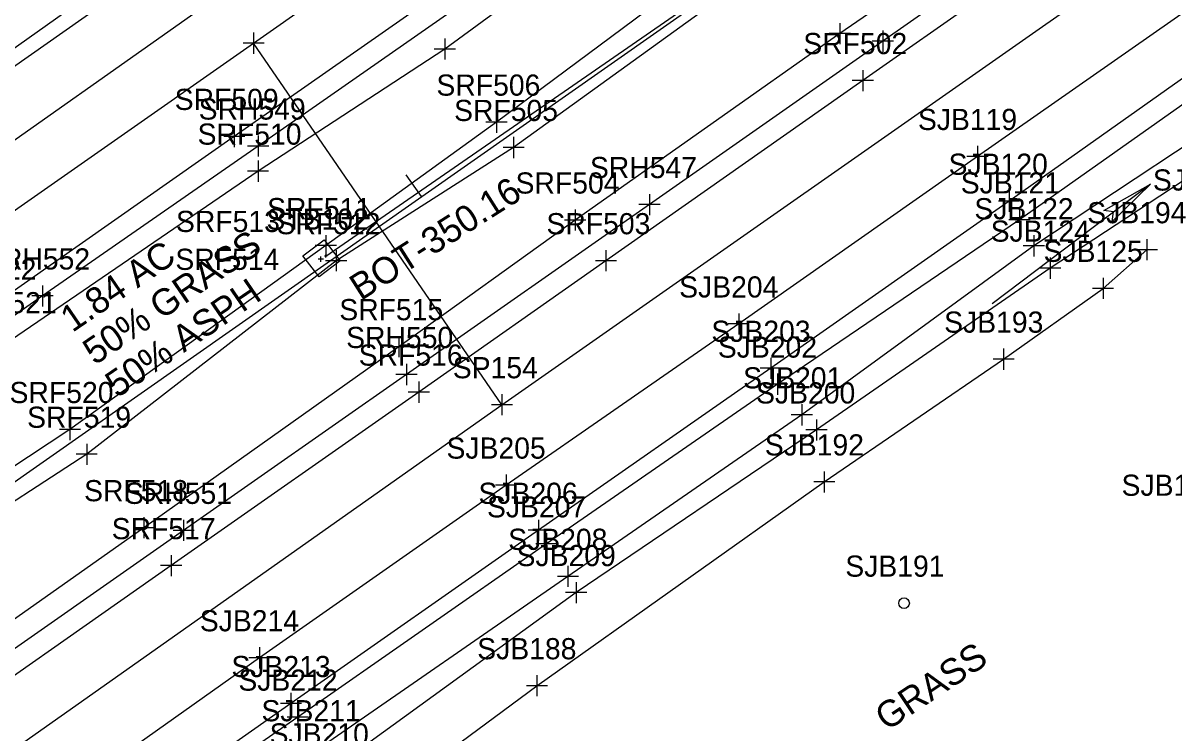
# Model space of a CAD drawing. Extents: x 941041 to 969446, y 397014 to 416764.
# Drawn here: x 951518.7 to 951736, y 402953.7 to 403087.8 of the extents above; entities that cross this region are included whole.
import ezdxf

# ---------------------------------------------------------------- set-up
doc = ezdxf.new("R2010")
doc.units = 0
for name, color, linetype in [('SURVEY - CENTERLINE - Preliminary', 7, 'Continuous'), ('SURVEY - CENTERLINE - Preliminary Curve Text', 7, 'Continuous'), ('SURVEY - DRAINAGE - Area Shapes', 7, 'Continuous'), ('SURVEY - DRAINAGE - Area Shapes - Points - Locators', 7, 'Continuous'), ('SURVEY - DRAINAGE - Area Shapes - Points - Numbers', 7, 'Continuous'), ('SURVEY - DRAINAGE - Area Shapes Text', 7, 'Continuous'), ('SURVEY - DRAINAGE - Pipes and Culverts', 7, 'Continuous'), ('SURVEY - DRAINAGE - Pipes and Culverts - Points - Locators', 7, 'Continuous'), ('SURVEY - DRAINAGE - Pipes and Culverts - Points - Numbers', 7, 'Continuous'), ('SURVEY - DRAINAGE - Storm Sewer', 7, 'Continuous'), ('SURVEY - DRAINAGE - Storm Sewer - Points - Numbers', 7, 'Continuous'), ('SURVEY - DTM - Breaklines', 7, 'Continuous'), ('SURVEY - DTM - Breaklines - Points - Locators', 7, 'Continuous'), ('SURVEY - DTM - Breaklines - Points - Numbers', 7, 'Continuous'), ('SURVEY - DTM - Spot Points - Locators', 7, 'Continuous'), ('SURVEY - DTM - Spot Points - Point Numbers', 7, 'Continuous'), ('SURVEY - MISCELLANEOUS - Bottom of MH and CB', 7, 'Continuous'), ('SURVEY - MISCELLANEOUS - Bottom of MH and CB - Points - Numbers', 7, 'Continuous'), ('SURVEY - TRANSPORTATION - Features', 7, 'Continuous'), ('SURVEY - TRANSPORTATION - Features - Points - Locators', 7, 'Continuous'), ('SURVEY - TRANSPORTATION - Features - Points - Numbers', 7, 'Continuous'), ('SURVEY - TRANSPORTATION - Roads', 7, 'Continuous'), ('SURVEY - TRANSPORTATION - Roads - Points - Locators', 7, 'Continuous'), ('SURVEY - TRANSPORTATION - Roads - Points - Numbers', 7, 'Continuous'), ('SURVEY - VEGETATION - Features with Text', 7, 'Continuous')]:
    doc.layers.add(name, color=color, linetype=linetype)

msp = doc.modelspace()

# ---------------------------------------------------------------- linework, layer by layer
at = {"layer": 'SURVEY - CENTERLINE - Preliminary'}
msp.add_line((950966.25, 402614.81), (953884.31, 404661.52), dxfattribs=at)
msp.add_line((950966.25, 402614.81), (953884.31, 404661.52), dxfattribs=at)
msp.add_line((950966.25, 402614.81), (953884.31, 404661.52), dxfattribs=at)
at = {"layer": 'SURVEY - CENTERLINE - Preliminary Curve Text'}
msp.add_line((951593.88, 403055.03), (951591.01, 403059.12), dxfattribs=at)
at = {"layer": 'SURVEY - DRAINAGE - Area Shapes'}
msp.add_line((951609.08, 403015.7), (951562.19, 403084.02), dxfattribs=at)
for points in [[(951145.6, 402792.15), (951562.19, 403084.02), (952475.83, 403724.71), (952754.77, 403922.8), (952578.99, 403846.21), (952455.44, 403792), (952334.19, 403750.29), (951972.51, 403632.53), (951887.41, 403584.59)], [(950765.73, 402528.11), (950855.07, 402487.28), (951056.09, 402625.14), (951609.08, 403015.7), (952524.78, 403657.05), (952475.83, 403724.71)]]:
    msp.add_lwpolyline(points, dxfattribs=at)
at = {"layer": 'SURVEY - DRAINAGE - Area Shapes - Points - Locators'}
for p, q in [((951562.19, 403086.02), (951562.19, 403082.02)), ((951564.19, 403084.02), (951560.19, 403084.02)), ((951609.08, 403017.7), (951609.08, 403013.7)), ((951611.08, 403015.7), (951607.08, 403015.7))]:
    msp.add_line(p, q, dxfattribs=at)
at = {"layer": 'SURVEY - DRAINAGE - Area Shapes Text'}
msp.add_line((951731.53, 403057.41), (951701.62, 403034.77), dxfattribs=at)
msp.add_lwpolyline([(951731.53, 403057.41), (951724.28, 403050.34), (951724.56, 403052.13), (951722.74, 403052.38)], close=True, dxfattribs=at)
msp.add_lwpolyline([(951731.53, 403057.41), (951724.28, 403050.34), (951724.56, 403052.13), (951722.74, 403052.38), (951731.53, 403057.41)], dxfattribs=at)
at = {"layer": 'SURVEY - DRAINAGE - Pipes and Culverts'}
msp.add_lwpolyline([(951575.84, 403043.76), (951765.83, 403175.23), (951951.92, 403216.39)], dxfattribs=at)
at = {"layer": 'SURVEY - DRAINAGE - Pipes and Culverts - Points - Locators'}
for p, q in [((951576.09, 403043.76), (951575.59, 403043.76)), ((951575.84, 403043.51), (951575.84, 403044.01)), ((951575.84, 403043.76), (951575.84, 403043.76)), ((951575.84, 403043.76), (951575.84, 403043.76))]:
    msp.add_line(p, q, dxfattribs=at)
at = {"layer": 'SURVEY - DRAINAGE - Storm Sewer'}
msp.add_line((951575.01, 403043.34), (951575.01, 403043.34), dxfattribs=at)
msp.add_lwpolyline([(951574.55, 403039.84), (951571.51, 403043.81), (951575.48, 403046.85), (951578.52, 403042.88), (951574.55, 403039.84)], dxfattribs=at)
at = {"layer": 'SURVEY - DTM - Breaklines'}
msp.add_line((951722.58, 403037.69), (951730.83, 403044.99), dxfattribs=at)
for points in [[(951854.25, 403319.66), (951811.69, 403290.89), (951768.65, 403259.5), (951723.04, 403227.57), (951679.29, 403196.14), (951634.6, 403164.93), (951590.23, 403133.88), (951544.48, 403102.6), (951498.11, 403069.66), (951452.15, 403038.35), (951433.07, 403025.21), (951424.63, 403019.72), (951420.03, 403018.11), (951422.38, 403023.89), (951430.59, 403035.7)], [(951836.08, 403227.91), (951793.18, 403197.31), (951749.92, 403170.47), (951703.64, 403135.64), (951660.15, 403107.9), (951608.06, 403069.1), (951575.82, 403045.76)], [(951839.65, 403222.38), (951797.17, 403192.37), (951753.33, 403165.09), (951706.67, 403131.34), (951664.15, 403102.54), (951611.28, 403064.31), (951577.76, 403042.92)], [(951882.64, 403166.97), (951846.32, 403142.14), (951845.34, 403140.85), (951800.52, 403105.06), (951758.25, 403071.51), (951712.6, 403041.51), (951668.47, 403010.93), (951623.1, 402980.2), (951576.62, 402946.49), (951535.08, 402916.86), (951489.08, 402884.22), (951442.46, 402851.9), (951396.06, 402820.24), (951353.64, 402790.7), (951305.86, 402756.61)], [(951846.17, 403143.63), (951798.24, 403106.85), (951755.36, 403076.11), (951709.52, 403045.74), (951665.69, 403013.78), (951621.55, 402983.27), (951574.76, 402950.88), (951533.18, 402922.12), (951486.76, 402887.78), (951441.32, 402857.8), (951393.85, 402824.12), (951350.68, 402794.89), (951304.42, 402761.09), (951261.65, 402730.04), (951245.94, 402719.49)], [(951575.82, 403045.76), (951527.52, 403011.01), (951480.03, 402979.65), (951432.25, 402944.1), (951384.56, 402912.98), (951337.64, 402877.72), (951288.98, 402848.05), (951240.98, 402812.92), (951195.6, 402783.43), (951143.39, 402744.95), (951093.24, 402715.77), (951046.95, 402677.96), (950999.14, 402648.78), (950948.74, 402611.17), (950902.47, 402579.09), (950854.68, 402542.03)], [(951577.76, 403042.92), (951530.68, 403006.34), (951482.65, 402975.12), (951435.54, 402939.25), (951387.56, 402907.68), (951341.21, 402872.58), (951293.73, 402840.01), (951246.54, 402805.47), (951199.41, 402776.68), (951147.67, 402739.07), (951099.33, 402706.23), (951051.58, 402671.4), (951004.7, 402639.99), (950954.22, 402602.88), (950907.42, 402570.91)], [(951291.86, 402744.42), (951338.46, 402771.86), (951384.81, 402800.53), (951428.6, 402828.85), (951473.25, 402860.72), (951518.66, 402892.2), (951567.96, 402927.23), (951615.69, 402962.6), (951669.94, 403001.11), (951703.81, 403024.31), (951722.58, 403037.69)]]:
    msp.add_lwpolyline(points, dxfattribs=at)
at = {"layer": 'SURVEY - DTM - Breaklines - Points - Locators'}
for p, q in [((951608.06, 403071.1), (951608.06, 403067.1)), ((951610.06, 403069.1), (951606.06, 403069.1)), ((951611.28, 403066.31), (951611.28, 403062.31)), ((951613.28, 403064.31), (951609.28, 403064.31)), ((951575.82, 403047.76), (951575.82, 403043.76)), ((951709.52, 403047.74), (951709.52, 403043.74)), ((951577.82, 403045.76), (951573.82, 403045.76)), ((951711.52, 403045.74), (951707.52, 403045.74)), ((951730.83, 403046.99), (951730.83, 403042.99)), ((951577.76, 403044.92), (951577.76, 403040.92)), ((951712.6, 403043.51), (951712.6, 403039.51)), ((951732.83, 403044.99), (951728.83, 403044.99)), ((951579.76, 403042.92), (951575.76, 403042.92)), ((951714.6, 403041.51), (951710.6, 403041.51)), ((951722.58, 403039.69), (951722.58, 403035.69)), ((951724.58, 403037.69), (951720.58, 403037.69)), ((951703.81, 403026.31), (951703.81, 403022.31)), ((951705.81, 403024.31), (951701.81, 403024.31)), ((951665.69, 403015.78), (951665.69, 403011.78)), ((951527.52, 403013.01), (951527.52, 403009.01)), ((951667.69, 403013.78), (951663.69, 403013.78)), ((951668.47, 403012.93), (951668.47, 403008.93)), ((951529.52, 403011.01), (951525.52, 403011.01)), ((951670.47, 403010.93), (951666.47, 403010.93)), ((951532.68, 403006.34), (951528.68, 403006.34)), ((951530.68, 403008.34), (951530.68, 403004.34)), ((951669.94, 403003.11), (951669.94, 402999.11)), ((951671.94, 403001.11), (951667.94, 403001.11)), ((951621.55, 402985.27), (951621.55, 402981.27)), ((951623.55, 402983.27), (951619.55, 402983.27)), ((951625.1, 402980.2), (951621.1, 402980.2)), ((951623.1, 402982.2), (951623.1, 402978.2)), ((951615.69, 402964.6), (951615.69, 402960.6)), ((951617.69, 402962.6), (951613.69, 402962.6))]:
    msp.add_line(p, q, dxfattribs=at)
at = {"layer": 'SURVEY - DTM - Spot Points - Locators'}
msp.add_circle((951685, 402978.2), 1, dxfattribs=at)
at = {"layer": 'SURVEY - MISCELLANEOUS - Bottom of MH and CB'}
for p, q in [((951574.9, 403042.68), (951574.9, 403043.68)), ((951575.4, 403043.18), (951574.4, 403043.18)), ((951574.9, 403043.18), (951574.9, 403043.18)), ((951574.9, 403043.18), (951574.9, 403043.18))]:
    msp.add_line(p, q, dxfattribs=at)
at = {"layer": 'SURVEY - TRANSPORTATION - Features'}
for points in [[(951846.55, 403258.26), (951803.24, 403226.1), (951748.25, 403189.15), (951693.85, 403151.36), (951652.28, 403122.5), (951598.3, 403082.91), (951563.02, 403059.84), (951516.46, 403027.98), (951469.63, 402994.87), (951420.56, 402960.47), (951375.73, 402928.74), (951325.75, 402893.61), (951279.89, 402861.42), (951230.97, 402826.96), (951186.74, 402796.51), (951134.07, 402759.39), (951086.9, 402726.09), (951037.69, 402691.08), (950990.96, 402659.35), (950941.16, 402624.61), (950894.08, 402591.27), (950846.1, 402558.07)], [(951856.72, 403212.68), (951764.5, 403147.89), (951717.58, 403116.6), (951672.86, 403085.82), (951622.89, 403050.6), (951589.61, 403026.67), (951541.47, 402992.46), (951493.88, 402958.88), (951445.62, 402924.24), (951399.07, 402891.81), (951350.72, 402858.88), (951303.21, 402826.01), (951256.16, 402792.29), (951210.71, 402760.72), (951159.21, 402724.85), (951109.63, 402690.18), (951062.08, 402656.92), (951014.84, 402623.15), (950965.73, 402588.73), (950917.42, 402555.24)], [(951845.47, 403150.79), (951794.85, 403112.74), (951750.76, 403081.68), (951706.8, 403050.62), (951661.08, 403019.6), (951617.49, 402989.41), (951570.55, 402956.66), (951529.62, 402928.23), (951481.56, 402894.72), (951437.37, 402863.29), (951389.55, 402829.63), (951347.66, 402799.3), (951299.97, 402764.93), (951259.62, 402733.33), (951238.85, 402716.85), (951240.37, 402714.07), (951266.38, 402722.33)]]:
    msp.add_lwpolyline(points, dxfattribs=at)
at = {"layer": 'SURVEY - TRANSPORTATION - Features - Points - Locators'}
for p, q in [((951672.86, 403087.82), (951672.86, 403083.82)), ((951598.3, 403084.91), (951598.3, 403080.91)), ((951674.86, 403085.82), (951670.86, 403085.82)), ((951600.3, 403082.91), (951596.3, 403082.91)), ((951563.02, 403061.84), (951563.02, 403057.84)), ((951565.02, 403059.84), (951561.02, 403059.84)), ((951622.89, 403052.6), (951622.89, 403048.6)), ((951706.8, 403052.62), (951706.8, 403048.62)), ((951624.89, 403050.6), (951620.89, 403050.6)), ((951708.8, 403050.62), (951704.8, 403050.62)), ((951589.61, 403028.67), (951589.61, 403024.67)), ((951591.61, 403026.67), (951587.61, 403026.67)), ((951661.08, 403021.6), (951661.08, 403017.6)), ((951663.08, 403019.6), (951659.08, 403019.6)), ((951541.47, 402994.46), (951541.47, 402990.46)), ((951543.47, 402992.46), (951539.47, 402992.46)), ((951617.49, 402991.41), (951617.49, 402987.41)), ((951619.49, 402989.41), (951615.49, 402989.41)), ((951570.55, 402958.66), (951570.55, 402954.66)), ((951572.55, 402956.66), (951568.55, 402956.66))]:
    msp.add_line(p, q, dxfattribs=at)
at = {"layer": 'SURVEY - TRANSPORTATION - Roads'}
for points in [[(951856.58, 403318.44), (951813.82, 403287.86), (951769.69, 403256.37), (951724.84, 403224.97), (951680.46, 403193.91), (951636.19, 403162.95), (951591.17, 403131.45), (951546.45, 403100.31), (951499.95, 403067.65), (951454.73, 403035.92), (951409.97, 403004.36), (951407.16, 403002.58), (951402.42, 402999.93), (951400.7, 402999.81), (951400.38, 403001.38), (951403.73, 403005.63), (951414.87, 403019.34), (951428.42, 403037.46)], [(951852.43, 403301), (951819.41, 403277.96), (951776.62, 403247.77), (951731.48, 403215.95), (951686.14, 403184.27), (951642.63, 403153.78), (951597.04, 403121.9), (951552.4, 403090.62), (951505.98, 403057.86), (951459.31, 403025.32), (951415.58, 402994.74), (951373.75, 402965.42), (951324.76, 402931.32), (951320.37, 402928.23), (951328.47, 402934.74), (951348.31, 402952.21), (951363.26, 402966.5), (951380.79, 402984.16), (951398.95, 403004.27), (951413.8, 403022.16), (951427.05, 403039.59)], [(951845.2, 403267.54), (951801.31, 403236.61), (951744.54, 403196.74), (951690.16, 403158.52), (951647.93, 403128.95), (951593.74, 403091.02), (951558.54, 403066.4), (951512.79, 403034.32), (951465.64, 403001.33), (951417.08, 402967.23), (951371.33, 402935.17), (951322.53, 402900.91), (951275.39, 402867.97), (951226.98, 402834.03), (951182.33, 402802.7), (951130.47, 402766.38), (951082.48, 402732.74), (951033.85, 402698.52), (950986.81, 402665.5), (950937.2, 402630.87), (950889.84, 402597.74), (950842.47, 402564.81)], [(951780.68, 403217.38), (951738.23, 403187.45), (951697.12, 403158.56), (951654.96, 403128.89), (951608.97, 403096.67), (951563.06, 403064.58), (951522.34, 403036.25), (951478.19, 403005.31), (951433.46, 402973.96), (951388.82, 402942.6), (951343.63, 402911.08), (951297.84, 402878.82), (951253.17, 402847.45), (951208.79, 402816.34), (951164.62, 402785.4), (951117.76, 402752.44), (951062.59, 402713.8), (951015.56, 402680.82), (950970.91, 402649.47), (950922.71, 402615.44), (950871.58, 402580), (950823.38, 402546.92)], [(951858.06, 403203.77), (951808.39, 403168.94), (951765.12, 403138.61), (951722.92, 403109), (951677.22, 403076.95), (951628.72, 403042.91), (951593.38, 403018.09), (951546.63, 402985.29), (951497.78, 402951.07), (951450.21, 402917.78), (951402.73, 402884.45), (951356.41, 402851.91), (951307.81, 402817.83), (951261.24, 402785.24), (951215.15, 402752.96), (951165.07, 402717.74), (951114.38, 402682.19), (951068.41, 402650.05), (951019.3, 402615.59), (950970.87, 402581.82), (950921.09, 402547.35)], [(951799.91, 403167.92), (951765.7, 403143.84), (951722.98, 403113.79), (951681.01, 403084.4), (951636.93, 403053.52), (951591.07, 403021.41), (951548.97, 402991.96), (951506.9, 402962.52), (951461.04, 402930.25), (951416.05, 402898.59), (951370.52, 402866.66), (951326.63, 402835.85), (951281.83, 402804.38), (951236.39, 402772.61), (951191.53, 402741.41), (951141.44, 402706.16), (951090.99, 402670.89), (951041.99, 402636.44), (950997.25, 402605.16), (950947.61, 402570.96)], [(951846.26, 403165.91), (951785.95, 403123.91), (951742.66, 403093.3), (951698.88, 403062.61), (951653.78, 403030.96), (951609.85, 403000.51), (951563.27, 402967.88), (951522.4, 402938.86), (951473.6, 402904.83), (951429.78, 402874.17), (951382.72, 402841.04), (951339.82, 402810.62), (951292.16, 402777.26), (951248.3, 402746.75), (951245.27, 402744.51), (951200.71, 402713.1), (951156.14, 402681.85), (951111.63, 402650.98), (951070.06, 402621.38)], [(951848.45, 403157.23), (951792.22, 403116.66), (951747.92, 403084.66), (951704.82, 403054.15), (951659.86, 403022.58), (951616, 402991.97), (951569.24, 402959.23), (951528.22, 402930.38), (951479.58, 402896.46), (951435.74, 402865.6), (951388.12, 402832.25), (951346.18, 402801.69), (951298.05, 402767.12), (951257.18, 402736.22), (951253.47, 402733.27), (951213.31, 402701.79), (951214.38, 402699.39), (951243.59, 402710.94), (951265.42, 402718.75)]]:
    msp.add_lwpolyline(points, dxfattribs=at)
at = {"layer": 'SURVEY - TRANSPORTATION - Roads - Points - Locators'}
for p, q in [((951681.01, 403086.4), (951681.01, 403082.4)), ((951683.01, 403084.4), (951679.01, 403084.4)), ((951677.22, 403078.95), (951677.22, 403074.95)), ((951679.22, 403076.95), (951675.22, 403076.95)), ((951558.54, 403068.4), (951558.54, 403064.4)), ((951560.54, 403066.4), (951556.54, 403066.4)), ((951563.06, 403066.58), (951563.06, 403062.58)), ((951565.06, 403064.58), (951561.06, 403064.58)), ((951698.88, 403064.61), (951698.88, 403060.61)), ((951700.88, 403062.61), (951696.88, 403062.61)), ((951636.93, 403055.52), (951636.93, 403051.52)), ((951706.82, 403054.15), (951702.82, 403054.15)), ((951704.82, 403056.15), (951704.82, 403052.15)), ((951638.93, 403053.52), (951634.93, 403053.52)), ((951628.72, 403044.91), (951628.72, 403040.91)), ((951630.72, 403042.91), (951626.72, 403042.91)), ((951522.34, 403038.25), (951522.34, 403034.25)), ((951524.34, 403036.25), (951520.34, 403036.25)), ((951653.78, 403032.96), (951653.78, 403028.96)), ((951655.78, 403030.96), (951651.78, 403030.96)), ((951659.86, 403024.58), (951659.86, 403020.58)), ((951591.07, 403023.41), (951591.07, 403019.41)), ((951661.86, 403022.58), (951657.86, 403022.58)), ((951593.07, 403021.41), (951589.07, 403021.41)), ((951593.38, 403020.09), (951593.38, 403016.09)), ((951595.38, 403018.09), (951591.38, 403018.09)), ((951609.85, 403002.51), (951609.85, 402998.51)), ((951611.85, 403000.51), (951607.85, 403000.51)), ((951548.97, 402993.96), (951548.97, 402989.96)), ((951616, 402993.97), (951616, 402989.97)), ((951550.97, 402991.96), (951546.97, 402991.96)), ((951618, 402991.97), (951614, 402991.97)), ((951546.63, 402987.29), (951546.63, 402983.29)), ((951548.63, 402985.29), (951544.63, 402985.29)), ((951563.27, 402969.88), (951563.27, 402965.88)), ((951565.27, 402967.88), (951561.27, 402967.88)), ((951569.24, 402961.23), (951569.24, 402957.23)), ((951571.24, 402959.23), (951567.24, 402959.23))]:
    msp.add_line(p, q, dxfattribs=at)

# ---------------------------------------------------------------- texts
at = {"layer": 'SURVEY - DRAINAGE - Area Shapes - Points - Numbers'}
msp.add_text('SP154', height=4, dxfattribs=at).set_placement((951599.8, 403020.7))
at = {"layer": 'SURVEY - DRAINAGE - Area Shapes Text'}
for s, p in [('50% GRASS', (951532.2, 403023.06)), ('1.84 AC', (951527.97, 403029.25)), ('50% ASPH', (951536.43, 403016.87))]:
    msp.add_text(s, height=4.998, rotation=34.3461, dxfattribs=at).set_placement(p)
at = {"layer": 'SURVEY - DRAINAGE - Pipes and Culverts - Points - Numbers'}
msp.add_text('STB102', height=4, dxfattribs=at).set_placement((951564.6, 403048.76))
at = {"layer": 'SURVEY - DRAINAGE - Storm Sewer - Points - Numbers'}
msp.add_text('SRF513', height=4, dxfattribs=at).set_placement((951547.53, 403048.34))
at = {"layer": 'SURVEY - DTM - Breaklines - Points - Numbers'}
for s, p in [('SRF506', (951596.71, 403074.1)), ('SRF505', (951600.04, 403069.31)), ('SRF511', (951564.74, 403050.76)), ('SJB122', (951698.28, 403050.74)), ('SRF512', (951566.52, 403047.92)), ('SJB194', (951719.59, 403049.99)), ('SJB124', (951701.36, 403046.51)), ('SJB125', (951711.34, 403042.69)), ('SJB193', (951692.57, 403029.31)), ('SJB201', (951654.61, 403018.78)), ('SRF520', (951516.11, 403016.01)), ('SJB200', (951657.06, 403015.93)), ('SRF519', (951519.42, 403011.34)), ('SJB192', (951658.7, 403006.11)), ('SJB208', (951610.26, 402988.27)), ('SJB209', (951611.84, 402985.2)), ('SJB188', (951604.41, 402967.6)), ('SJB211', (951563.67, 402955.88)), ('SJB210', (951565.21, 402951.49))]:
    msp.add_text(s, height=4, dxfattribs=at).set_placement(p)
at = {"layer": 'SURVEY - DTM - Spot Points - Point Numbers'}
for s, p in [('SJB126', (951731.99, 403056.17)), ('SJB195', (951726.07, 402998.49)), ('SJB191', (951673.91, 402983.2))]:
    msp.add_text(s, height=4, dxfattribs=at).set_placement(p)
at = {"layer": 'SURVEY - MISCELLANEOUS - Bottom of MH and CB'}
msp.add_text('BOT-350.16', height=5, rotation=32.4234, dxfattribs=at).set_placement((951582.42, 403035.24))
at = {"layer": 'SURVEY - MISCELLANEOUS - Bottom of MH and CB - Points - Numbers'}
msp.add_text('SRF514', height=4, dxfattribs=at).set_placement((951547.42, 403041.18))
at = {"layer": 'SURVEY - TRANSPORTATION - Features - Points - Numbers'}
for s, p in [('SRF510', (951551.61, 403064.84)), ('SRF504', (951611.65, 403055.6)), ('SJB121', (951695.71, 403055.62)), ('SRF521', (951505.38, 403032.98)), ('SRF515', (951578.37, 403031.67)), ('SJB202', (951649.84, 403024.6)), ('SRF518', (951530.18, 402997.46)), ('SJB207', (951606.25, 402994.41)), ('SJB212', (951559.31, 402961.66))]:
    msp.add_text(s, height=4, dxfattribs=at).set_placement(p)
at = {"layer": 'SURVEY - TRANSPORTATION - Roads - Points - Numbers'}
for s, p in [('SRF502', (951665.98, 403081.95)), ('SRF509', (951547.29, 403071.4)), ('SRH549', (951551.81, 403069.58)), ('SJB119', (951687.62, 403067.61)), ('SJB120', (951693.41, 403059.15)), ('SRH547', (951625.69, 403058.52)), ('SRF503', (951617.48, 403047.91)), ('SRF522', (951501.55, 403039.32)), ('SRH552', (951511.1, 403041.25)), ('SJB204', (951642.54, 403035.96)), ('SRH550', (951579.66, 403026.41)), ('SJB203', (951648.62, 403027.58)), ('SRF516', (951582.03, 403023.09)), ('SJB205', (951598.61, 403005.51)), ('SRH551', (951537.89, 402996.96)), ('SJB206', (951604.65, 402996.97)), ('SRF517', (951535.39, 402990.29)), ('SJB214', (951552.03, 402972.88)), ('SJB213', (951558, 402964.23))]:
    msp.add_text(s, height=4, dxfattribs=at).set_placement(p)
at = {"layer": 'SURVEY - VEGETATION - Features with Text'}
msp.add_text('GRASS', height=4.998, rotation=33.7585, dxfattribs=at).set_placement((951681.73, 402953.94))

doc.saveas('drawing.dxf')
